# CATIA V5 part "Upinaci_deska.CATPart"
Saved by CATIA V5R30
Part number: Upinaci_deska
Definition: F 10_346446_36_1730_2
Nomenclature: F 10_346446_36_1730_2
Source: Unknown
Description: PART--DESC
Bounding box of the stored display mesh (mm): x -223 to 223, y -198 to 198, z -260 to -224
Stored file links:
  E:\Bakalarka\Model\Forma_v7\Upinaci_deska.CATPart
  E:\Bakalarka\Model\Forma_v7\Vyhazovaci_cast.CATProduct
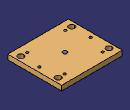
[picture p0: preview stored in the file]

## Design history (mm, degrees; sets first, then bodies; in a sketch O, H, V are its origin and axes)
Set1
  Sketch1 on face of Solid1, origin (0, 0, -260), H (1, 0, 0), V (0, -1, 0)
    point P1 (188, 0)
    point P2 (-188, 0)
    reference projected line E1 (223, -198) -> (223, 198) from edge [face of Solid1 | face of Solid1]
    reference projected line E2 (-223, 198) -> (-223, -198) from edge [face of Solid1 | face of Solid1]
    distance P1 E1 = 35
    distance E2 P2 = 35
    coincidence: P1 H, P2 H
Body1 "MANIFOLD_SOLID_BREP #3986" (main body)
  Solid1: solid without history
  Body2 "Result of TapHole"
    Solid2: linked copy from another document
  Assemble1 "TapHoleCapScrew_E1200_1.1": tool Body2
  Body3 "Result of TapHole"
    Solid3: linked copy from another document
  Assemble2 "TapHoleCapScrew_E1200_1.2": tool Body3
  Sketch2 on face of Solid1, origin (0, 0, -256), H (1, 0, 0), V (0, -1, 0)
    circle A1 centre (0, 0) radius 15
    radius A1 = 15
  Pocket1: profile Sketch2, direction (0, 0, 1), through (limit type 6)
  Body4 "Result of TapHole"
    Solid4: linked copy from another document
  Assemble3 "TapHoleCountersunkScrew_E1220_6.1": tool Body4
  Body5 "Result of TapHole"
    Solid5: linked copy from another document
  Assemble4 "TapHoleCountersunkScrew_E1220_6.2": tool Body5
  Body6 "Result of TapHole"
    Solid6: linked copy from another document
  Assemble5 "TapHoleCountersunkScrew_E1220_6.3": tool Body6
  Body7 "Result of TapHole"
    Solid7: linked copy from another document
  Assemble6 "TapHoleCountersunkScrew_E1220_6.4": tool Body7
  Body8 "Result of DrillHole"
    Solid8: linked copy from another document
  Assemble7 "DrillHoleLeaderPin_E1010_1.1": tool Body8
  Body9 "Result of DrillHole"
    Solid9: linked copy from another document
  Assemble8 "DrillHoleLeaderPin_E1010_1.2": tool Body9
  Body10 "Result of DrillHole"
    Solid10: linked copy from another document
  Assemble9 "DrillHoleLeaderPin_E1010_1.3": tool Body10
  Body11 "Result of DrillHole"
    Solid11: linked copy from another document
  Assemble10 "DrillHoleLeaderPin_E1010_1.4": tool Body11
  Sketch3 on face of Solid1, origin (0, 0, -260), H (1, 0, 0), V (0, -1, 0)
    reference projected circle E1 centre (188, 0) radius 13 from edge [face of Solid1 | face of Solid8]
    reference projected circle E2 centre (-188, 0) radius 13 from edge [face of Solid1 | face of Solid9]
    point P1 (188, 0)
    point P2 (-188, 0)
    concentricity: P1 E1, P2 E2
Body12 "Result of DrillHole"
  Solid12: linked copy from another document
